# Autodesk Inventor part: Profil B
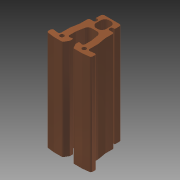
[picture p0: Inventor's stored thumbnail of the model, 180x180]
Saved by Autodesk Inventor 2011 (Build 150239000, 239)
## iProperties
Created: 2010-03
Part Number: Profil B
Document SubType Name: Modeling
Designer: ehttln
Density: 8.94 g/cm^3
Material: Cast Copper
Description: Profile Type B
Mass: 79.2782 g
Surface Area: 79.9496 cm^2
Volume: 8.86781 cm^3
Author: ehttln
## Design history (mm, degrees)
sketch "Sketch1"
  geometry: L1 (-6.364, -5.908)-(-6.357, -5.911); L2 (-1.315, -5.111)-(-1.326, -5.113); L3 (1.314, -5.111)-(-1.315, -5.111); L4 (1.297, -5.113)-(1.314, -5.111); L5 (-3.277, -6.75)-(-3.258, -6.749); L6 (-7.107, -10.229)-(-6.37, -6.038); L7 (-3.932, -10.509)-(-3.94, -10.505); L8 (-3.951, -10.642)-(-3.944, -10.636); L9 (-3.258, -6.749)-(-3.932, -10.509); L10 (-7.126, -14.693)-(-7.119, -14.687); L11 (-7.119, -18.345)-(-10.421, -17.938); L12 (-10.421, -17.938)-(-10.436, -17.94); L13 (-10.231, -15.195)-(-7.963, -15.478); L14 (-10.244, -15.2)-(-10.231, -15.195); L15 (-11.127, -17.159)-(-11.12, -17.163); L16 (-11.12, -17.163)-(-11.12, -15.982); L17 (-11.12, -15.982)-(-11.127, -15.981); L18 (-3.163, -18.345)-(-7.119, -18.345); L19 (3.894, -1.555)-(5.581, -1.555); L20 (5.581, -1.555)-(5.574, -1.557); L21 (7.105, -14.687)-(7.098, -14.693); L22 (7.981, -15.474)-(7.994, -15.474); L23 (10.229, -15.195)-(10.215, -15.2); L24 (7.994, -15.474)-(10.229, -15.195); L25 (10.429, -17.937)-(7.105, -18.345); L26 (11.105, -17.163)-(11.098, -17.159); L27 (11.105, -15.982)-(11.105, -17.163); L28 (11.098, -15.981)-(11.105, -15.982); L29 (-3.754, 3.728)-(3.739, 3.728); L30 (-3.182, -0.768)-(-3.182, -0.438); L31 (-3.189, -0.77)-(-3.182, -0.768); L32 (-3.182, -0.438)-(-3.189, -0.439); L33 (-3.977, 0.348)-(-3.97, 0.35); L34 (-4.77, 0.35)-(-4.77, 2.712); L35 (-4.77, 2.712)-(-4.777, 2.71); L36 (-3.761, 3.726)-(-3.754, 3.728); L37 (-3.027, -14.495)-(-3.017, -14.496); L38 (-2.522, -17.951)-(-2.535, -17.953); L39 (-1.493, -16.173)-(-2.522, -17.951); L40 (-3.017, -14.496)-(-1.684, -14.255); L41 (-1.684, -14.255)-(-1.697, -14.261); L42 (-1.399, -14.511)-(-1.392, -14.509); L43 (-1.392, -14.509)-(-1.392, -15.779); L44 (-1.392, -15.779)-(-1.399, -15.773); L45 (-1.504, -16.167)-(-1.493, -16.173); L46 (-6.37, -6.038)-(-6.376, -6.045); L47 (6.336, -2.319)-(6.343, -2.317); L48 (6.343, -5.911)-(6.336, -5.908); L49 (6.343, -2.317)-(6.343, -5.911); L50 (6.348, -6.044)-(6.355, -6.038); L51 (3.257, -6.749)-(3.248, -6.75); L52 (6.355, -6.038)-(7.092, -10.229); L53 (3.917, -10.509)-(3.257, -6.749); L54 (7.105, -10.369)-(7.105, -14.687); L55 (7.098, -10.364)-(7.105, -10.369); L56 (7.092, -10.229)-(7.086, -10.227); L57 (3.93, -13.722)-(3.93, -10.636); L58 (3.93, -10.636)-(3.923, -10.642); L59 (3.911, -10.505)-(3.917, -10.509); L60 (-7.115, -10.227)-(-7.107, -10.229); L61 (-7.119, -10.369)-(-7.126, -10.364); L62 (-7.119, -14.687)-(-7.119, -10.369); L63 (-3.944, -13.722)-(-3.951, -13.72); L64 (-3.944, -10.636)-(-3.944, -13.722)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; C1 r 1 at (-5.602, -15.773); C2 r 1 at (5.574, -15.773); A1 r 1.981 centre (-1.326, -7.094) between (-1.326, -5.113) and (-3.277, -6.75); A2 r 0.787 centre (-3.164, -10.642) between (-3.94, -10.505) and (-3.951, -10.642); A3 r 0.787 centre (-7.914, -14.693) between (-7.963, -15.478) and (-7.126, -14.693); A4 r 0.787 centre (-10.34, -17.159) between (-11.127, -17.159) and (-10.436, -17.94); A5 r 0.787 centre (-10.34, -15.981) between (-10.244, -15.2) and (-11.127, -15.981); A6 r 0.787 centre (-3.164, -13.72) between (-3.951, -13.72) and (-3.027, -14.495); A7 r 0.787 centre (3.948, -0.77) between (3.161, -0.77) and (3.894, -1.555); A8 r 0.762 centre (5.574, -2.319) between (6.336, -2.319) and (5.574, -1.557); A9 r 0.787 centre (7.885, -14.693) between (7.098, -14.693) and (7.981, -15.474); A10 r 0.787 centre (10.311, -15.981) between (11.098, -15.981) and (10.215, -15.2); A11 r 0.787 centre (10.311, -17.159) between (10.429, -17.937) and (11.098, -17.159); A12 r 1.016 centre (-3.761, 2.71) between (-3.761, 3.726) and (-4.777, 2.71); A13 r 0.787 centre (-3.217, -17.559) between (-3.163, -18.345) and (-2.535, -17.953); A14 r 0.254 centre (-1.653, -14.511) between (-1.399, -14.511) and (-1.697, -14.261); A15 r 0.787 centre (-2.186, -15.773) between (-1.504, -16.167) and (-1.399, -15.773); A16 r 0.787 centre (-7.152, -5.908) between (-6.376, -6.045) and (-6.364, -5.908); A17 r 0.787 centre (7.123, -5.908) between (6.336, -5.908) and (6.348, -6.044); A18 r 1.981 centre (1.297, -7.094) between (3.248, -6.75) and (1.297, -5.113); A19 r 0.787 centre (6.31, -10.364) between (7.098, -10.364) and (7.086, -10.227); A20 r 0.787 centre (3.135, -10.642) between (3.923, -10.642) and (3.911, -10.505); A21 r 0.787 centre (-6.339, -10.364) between (-7.115, -10.227) and (-7.126, -10.364); A22 r 1.016 centre (3.732, 2.71) between (4.748, 2.71) and (3.732, 3.726); A23 r 0.787 centre (3.948, -0.439) between (3.948, 0.348) and (3.161, -0.439); A24 r 0.787 centre (-3.977, -0.77) between (-4.031, -1.555) and (-3.189, -0.77); A25 r 0.762 centre (-5.602, -2.319) between (-5.602, -1.557) and (-6.364, -2.319); A26 r 0.787 centre (-3.977, -0.439) between (-3.189, -0.439) and (-3.977, 0.348); A27 r 0.787 centre (3.135, -13.72) between (3.052, -14.503) and (3.923, -13.72); A28 r 0.787 centre (3.188, -17.559) between (2.506, -17.953) and (3.188, -18.346); A29 r 0.254 centre (1.624, -14.511) between (1.668, -14.261) and (1.377, -14.451); A30 r 0.787 centre (2.157, -15.773) between (1.37, -15.773) and (1.475, -16.167); A31 r 2.163 centre (-0.414, -1.76) between (-2.577, -1.76) and (-0.414, -3.923); A32 r 2.163 centre (0.414, -1.76) between (0.414, -3.923) and (2.577, -1.76); A33 r 2.163 centre (-0.414, 0.593) between (-0.414, 2.756) and (-2.577, 0.593); A34 r 2.163 centre (0.414, 0.593) between (2.577, 0.593) and (0.414, 2.756); 2 further points
  constraints: 182 end point, 68 point on circle, 36 centre point, 8 tangent, 3 equal radius, 2 parallel, 1 horizontal, 1 midpoint, 1 perpendicular, 1 vertical alignment
  dimensions: "d6" = 2 diameter of C1; "d7" = 2 diameter of C2
extrude "Extrusion1" new body sketch "Sketch1" distance "d0" = 50; taper "d1" = 0 deg
body "Solid1"
